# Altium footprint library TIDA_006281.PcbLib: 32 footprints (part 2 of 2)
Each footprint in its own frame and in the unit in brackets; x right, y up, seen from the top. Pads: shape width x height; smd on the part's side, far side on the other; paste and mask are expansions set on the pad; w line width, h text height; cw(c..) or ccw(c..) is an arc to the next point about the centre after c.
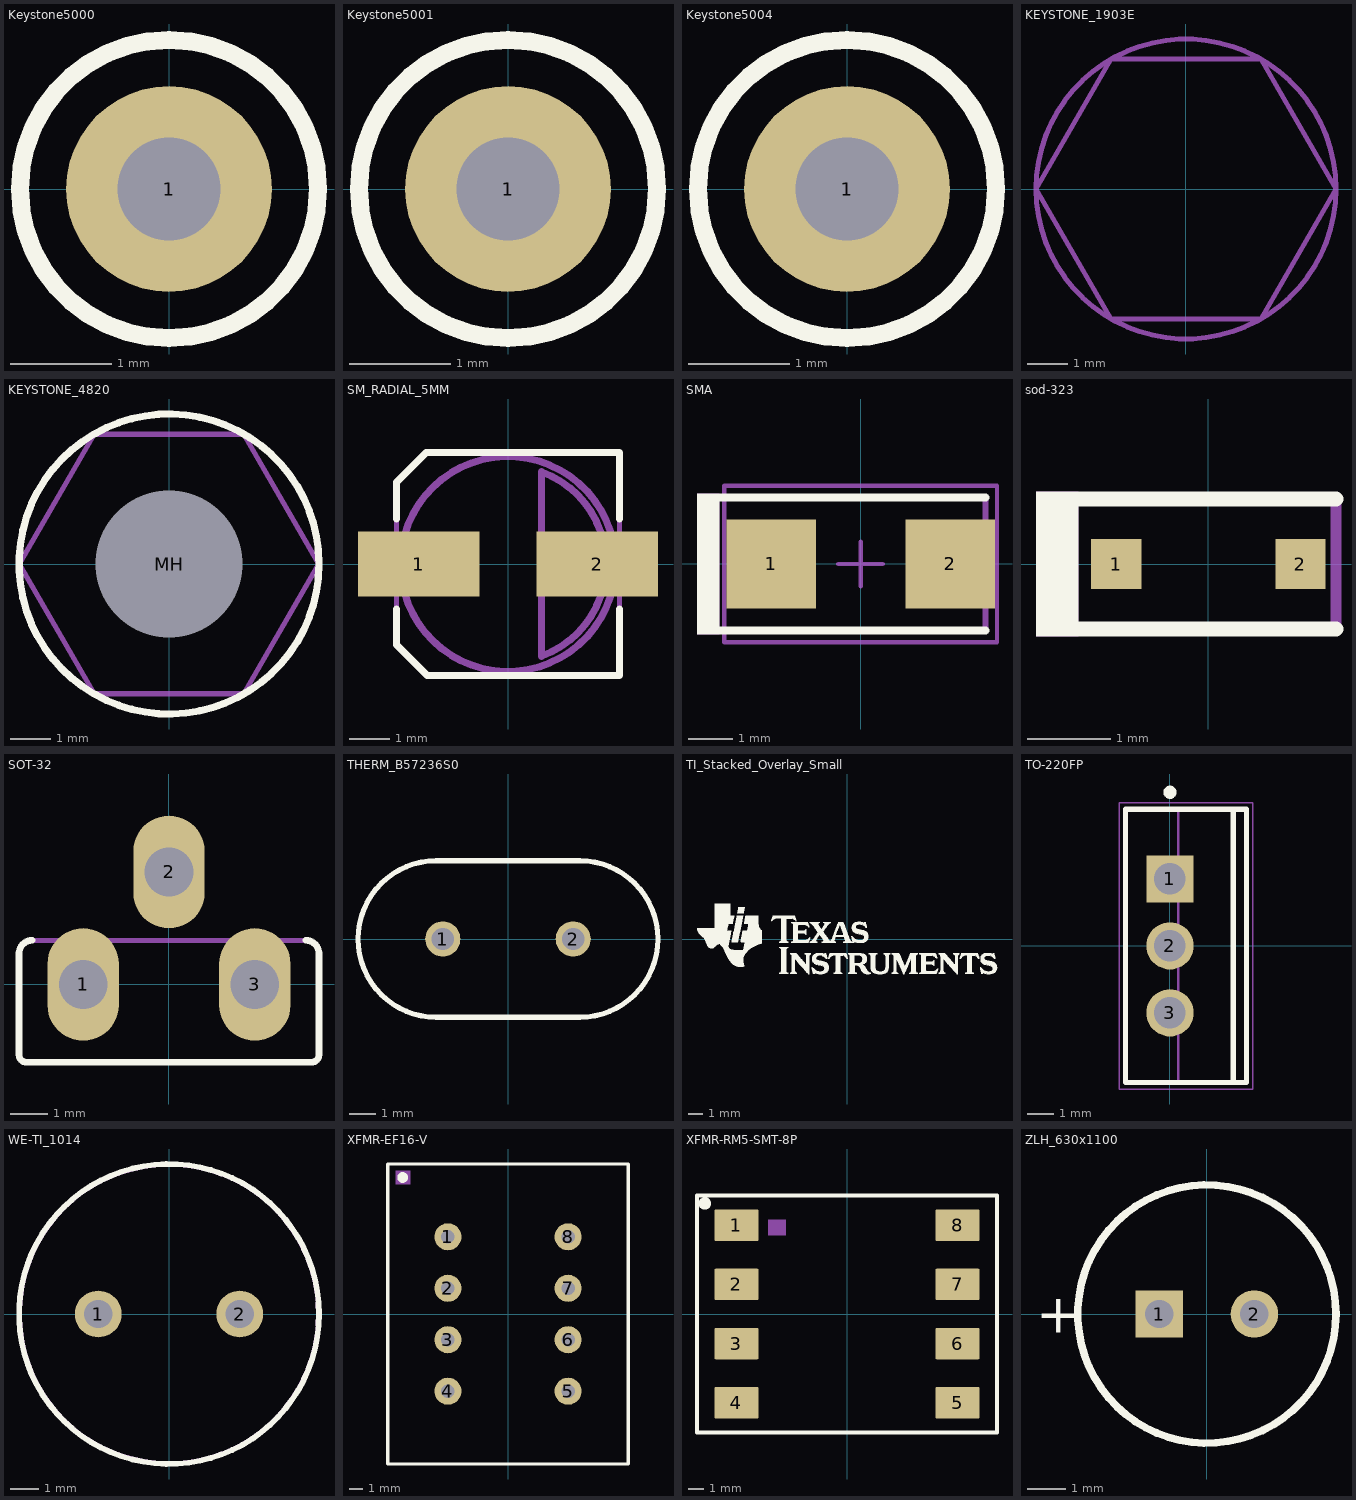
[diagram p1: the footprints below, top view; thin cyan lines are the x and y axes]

## Keystone5000 [mil] "For Keystone 500x miniature loop terminals"
height 181.1
pads (1):
  round 80 hole 40: 1(0,0)
Top Overlay:
  circle w7: c0,0 r58
Mechanical 5:
  circle w5: c0,0 r58.31
  text ".Designator" at -45,-10 h30
3D body: height 181.97, standoff -118.11, extent -49,-49 49.04,49.23

## Keystone5001 [mil] "For Keystone 500x miniature loop terminals"
height 181.1
pads (1):
  round 80 hole 40: 1(0,0)
Top Overlay:
  circle w7: c0,0 r58
Mechanical 5:
  circle w5: c0,0 r58.31
  text ".Designator" at -45,-10 h30
3D body: height 181.97, standoff -118.11, extent -49,-49 49.04,49.24

## Keystone5004 [mil] "For Keystone 500x miniature loop terminals"
height 181.1
pads (1):
  round 80 hole 40: 1(0,0)
Top Overlay:
  circle w7: c0,0 r58
Mechanical 5:
  circle w5: c0,0 r58.31
  text ".Designator" at -45,-10 h30
3D body: height 181.97, standoff -118.11, extent -49,-49 49.04,49.23

## KEYSTONE_1903E [mil] "HEX NYLON STANDOFF 6-32, F-F 1\""
height 1000
pads (1):
  round 1 on Mech3: 0(0,0)
Mechanical 5:
  circle w5: c0,0 r147.71
  lines w5: -147.75,-0.05 -73.87,127.91 73.87,127.91 147.75,-0.05 73.87,-128 -73.87,-128 -147.75,-0.05
  text ".Designator" at -75,-19 h40
3D body: height 1000, standoff 0, extent -147.74,-127.95 147.75,127.96

## KEYSTONE_4820 [mm] "HEX NYLON STANDOFF 6-32, M-F 1\""
height 25.4
pads (2):
  round 0.025 on Mech3: 0(0,0)
  round 1 hole 3.6 unplated: MH(0,0)
Top Overlay:
  circle w0.178: c0,0 r3.67
Mechanical 5:
  circle w0.127: c0,0 r3.67
  lines w0.127: -3.666,0 -1.833,3.175 1.833,3.175 3.666,0 1.833,-3.175 -1.833,-3.175 -3.666,0
  text ".Designator" at -1.829,-0.457 h1.02
3D body: height 25.42, standoff -6.33, extent -3.666,-3.175 3.666,3.175

## SM_RADIAL_5MM [mm] "Nichicon 5x5.8"
height 6.1
pads (2):
  rect 3x1.6 smd: 1(-2.2,0) 2(2.2,0)
Top Overlay:
  lines w0.178: -2.75,-1.108 -2.75,-1.992 -1.992,-2.75 2.75,-2.75 2.75,-1.108 ; -2.75,1.108 -2.75,2.019 -2.019,2.75 2.75,2.75 2.75,1.118
Mechanical 5:
  lines w0.127: -2.75,-1.992 -2.75,2.019 -2.019,2.75 2.75,2.75 2.75,-2.75 -1.992,-2.75 -2.75,-1.992
  text ".Designator" at -1.9,-0.5 h1.02
Mechanical 13:
  circle w0.178: c0,0 r2.65
  lines w0.178: 0.827,-2.273 ccw(c0,0) 0.827,2.273 0.827,-2.273
3D body: height 6.1, standoff 1, extent -2.658,-2.658 2.658,2.658
3D body: height 6.1, standoff 6, extent 0.827,-2.277 2.432,2.277
3D body: height 1, standoff 0, extent -2.751,-2.751 2.751,2.751

## SMA [mm] "Molded Diode, 2-Leads, Body 4.3x2.6mm, IPC Medium Density, based on OnSemi component dimensions and land pattern"
height 2.27
pads (2):
  rect 2x2 smd: 1(-2,0) 2(2,0)
Top Overlay:
  rectangle: -3.658,-1.575 -3.15,1.575
  lines w0.178: -3.327,-1.486 2.794,-1.486 ; -3.327,1.486 2.794,1.486
Mechanical 5:
  rectangle: -3.658,-1.575 -3.15,1.575
  lines w0.127: -3.327,-1.486 2.794,-1.486 2.794,1.486 -3.327,1.486
  text ".Designator" at -2.769,-0.33 h1.02
Mechanical 15:
  lines w0.1: -0.5,0 0.5,0 ; 0,-0.5 0,0.5 ; -3.05,-1.75 -3.05,1.75 3.05,1.75 3.05,-1.75 -3.05,-1.75
3D body: height 2.42, standoff 0.02, extent -2.6,-1.3 2.6,1.3

## sod-323 [mm] "NXP recommended land pattern"
height 1.15
pads (2):
  rect 0.6x0.6 smd paste-0.05: 1(-1.1,0) 2(1.1,0)
Top Overlay:
  rectangle: -2.057,-0.864 -1.549,0.864
  lines w0.178: -1.803,-0.775 0.1,-0.775 1.525,-0.775 ; -1.803,0.775 0.1,0.775 1.525,0.775
Mechanical 5:
  rectangle: -2.057,-0.864 -1.549,0.864
  lines w0.127: -1.803,-0.775 0.1,-0.775 1.525,-0.775 1.525,0.775 0.1,0.775 -1.803,0.775
  text ".Designator" at -1.4,-0.275 h0.76
3D body: height 1.1, standoff 0, extent -1.3,-0.675 1.3,0.675

## SOT-32 [mm]
height 13
pads (3):
  oval 1.9x3 hole 1.3: 1(-2.29,0) 2(0,3) 3(2.29,0)
Top Overlay:
  lines w0.178: -3.65,1.175 ccw(c-3.65,0.825) -3.996,0.878 ccw(c-3.65,0.825) -4,0.825 -4,-1.845 -4,-1.875 ccw(c-3.8,-1.875) -3.8,-2.075 3.8,-2.075 ccw(c3.8,-1.875) 4,-1.875 4,-1.845 4,0.825 ccw(c3.65,0.825) 3.996,0.878 ccw(c3.65,0.825) 3.65,1.175
Mechanical 5:
  lines w0.127: -4,-1.875 ccw(c-3.8,-1.875) -3.8,-2.075 3.8,-2.075 ccw(c3.8,-1.875) 4,-1.875 4,-1.845 4,0.825 ccw(c3.65,0.825) 3.996,0.878 ccw(c3.65,0.825) 3.65,1.175 -3.65,1.175 ccw(c-3.65,0.825) -3.996,0.878 ccw(c-3.65,0.825) -4,0.825 -4,-1.845 -4,-1.875
  text ".Designator" at -1.875,-0.5 h1.02
3D body: height 13.13, standoff -4.98, extent -4,-2.073 4,1.177

## THERM_B57236S0 [mm] "EPCOS"
height 16
pads (2):
  round 1.35 hole 0.85: 1(-2.5,0) 2(2.5,0)
Top Overlay:
  lines w0.2: -2.75,-3 cw(c-2.75,0) -2.75,3 2.75,3 cw(c2.75,0) 2.75,-3 -2.75,-3
Mechanical 5:
  lines w0.1: -2.75,-3 cw(c-2.75,0) -2.75,3 2.75,3 cw(c2.75,0) 2.75,-3 -2.75,-3
  text ".Designator" at -4.024,-0.508 h1.02
3D body: height 15.99, standoff 4.51, extent -5.755,-3 5.7,3
3D body: height 5.5, standoff -2.5, extent 2.202,-0.299 2.8,0.3
3D body: height 5.5, standoff -2.5, extent -2.797,-0.299 -2.2,0.3

## TI_Stacked_Overlay_Small [mm]
Top Overlay:
  drawing of 18 lines, arcs and shapes, not listed

## TO-220FP [mm] "FM, Body 10.4x4.6mm, Pitch 2.55mm"
height 20
pads (3):
  rect 1.8x1.8 hole 1.2: 1(0,2.55)
  round 1.8 hole 1.2: 2(0,0) 3(0,-2.55)
Top Overlay:
  circle w0.25: c0,5.85 r0.125
  lines w0.2: 2.41,-5.2 2.41,5.2 ; -1.69,-5.2 -1.69,5.2 2.91,5.2 2.91,-5.2 -1.69,-5.2
Mechanical 5:
  lines w0.1: 0.31,-5.2 0.31,5.2 ; -1.69,-5.2 2.91,-5.2 2.91,5.2 -1.69,5.2 -1.69,-5.2
  text ".Designator" at 1.1,1.6 h1.02
Mechanical 15:
  lines w0.05: -1.94,-5.45 3.16,-5.45 3.16,5.45 -1.94,5.45 -1.94,-5.45
  lines w0.1: -0.5,0 0.5,0 ; 0,-0.5 0,0.5
3D body: height 20, standoff 18.15, extent 0.31,-5.1 2.91,5.1
3D body: height 16.91, standoff 16.6, extent 0.31,-5.1 2.91,-1.55
3D body: height 16.91, standoff 16.6, extent 0.31,1.55 2.91,5.1
3D body: height 16.6, standoff 16.3, extent 0.31,-5.1 2.91,-1.55
3D body: height 16.6, standoff 16.3, extent 0.31,1.55 2.91,5.1
3D body: height 17.2, standoff 16.9, extent 0.31,-5.1 2.91,-1.52
3D body: height 17.2, standoff 16.9, extent 0.31,1.52 2.91,5.1
3D body: height 16.3, standoff 16.01, extent 0.31,-5.1 2.91,-1.52
3D body: height 16.3, standoff 16.01, extent 0.31,1.52 2.91,5.1
3D body: height 17.47, standoff 17.19, extent 0.31,-5.1 2.91,-1.432
3D body: height 17.47, standoff 17.19, extent 0.31,1.432 2.91,5.1
3D body: height 16.01, standoff 15.74, extent 0.31,-5.1 2.91,-1.432
3D body: height 16.01, standoff 15.74, extent 0.31,1.432 2.91,5.1
3D body: height 17.7, standoff 17.46, extent 0.31,-5.1 2.91,-1.289
3D body: height 17.7, standoff 17.46, extent 0.31,1.289 2.91,5.1
3D body: height 15.74, standoff 15.5, extent 0.31,-5.1 2.91,-1.289
3D body: height 15.74, standoff 15.5, extent 0.31,1.289 2.91,5.1
3D body: height 17.89, standoff 17.7, extent 0.31,-5.1 2.91,-1.096
3D body: height 17.89, standoff 17.7, extent 0.31,1.096 2.91,5.1
3D body: height 15.51, standoff 15.31, extent 0.31,-5.1 2.91,-1.096
3D body: height 15.51, standoff 15.31, extent 0.31,1.096 2.91,5.1
3D body: height 18.04, standoff 17.89, extent 0.31,-5.1 2.91,-0.861
3D body: height 18.04, standoff 17.89, extent 0.31,0.861 2.91,5.1
3D body: height 15.32, standoff 15.17, extent 0.31,-5.1 2.91,-0.861
3D body: height 15.32, standoff 15.17, extent 0.31,0.861 2.91,5.1
3D body: height 18.13, standoff 18.03, extent 0.31,-5.1 2.91,-0.593
3D body: height 18.13, standoff 18.03, extent 0.31,0.593 2.91,5.1
3D body: height 15.17, standoff 15.08, extent 0.31,-5.1 2.91,-0.593
3D body: height 15.17, standoff 15.08, extent 0.31,0.593 2.91,5.1
3D body: height 18.15, standoff 18.12, extent 0.31,-5.1 2.91,-0.302
3D body: height 18.15, standoff 18.12, extent 0.31,0.302 2.91,5.1
3D body: height 15.08, standoff 15.05, extent 0.31,-5.1 2.91,-0.302
3D body: height 15.08, standoff 15.05, extent 0.31,0.302 2.91,5.1
3D body: height 15.05, standoff 13, extent 0.31,-5.1 2.91,5.1
3D body: height 13, standoff 2.5, extent -1.69,-5.2 2.91,5.2
3D body: height 0, standoff -1.6, extent -0.29,-2.99 0.29,-2.11
3D body: height 2.5, standoff 0, extent -0.29,-3.265 0.29,-1.835
3D body: height 0, standoff -1.6, extent -0.29,-0.44 0.29,0.44
3D body: height 2.5, standoff 0, extent -0.29,-0.715 0.29,0.715
3D body: height 0, standoff -1.6, extent -0.29,2.11 0.29,2.99
3D body: height 2.5, standoff 0, extent -0.29,1.835 0.29,3.265

## WE-TI_1014 [mm] "WURTH"
height 14.5
pads (2):
  round 1.65 hole 1: 1(-2.5,0) 2(2.5,0)
Top Overlay:
  circle w0.2: c0,0 r5.3
Mechanical 5:
  circle w0.1: c0,0 r5.25
  text ".Designator" at -1.8,-0.5 h1.02
3D body: height 14.5, standoff 13.5, extent -5.261,-5.261 5.261,5.261
3D body: height 13.5, standoff 4, extent -4.91,-4.91 4.91,4.91
3D body: height 4, standoff 0, extent -5.261,-5.261 5.261,5.261
3D body: height 1, standoff -2, extent -2.847,-0.349 -2.15,0.35
3D body: height 1, standoff -2, extent 2.153,-0.349 2.85,0.35

## XFMR-EF16-V [mm]
pads (8):
  round 2 hole 1: 1(-4.445,5.715) 2(-4.445,1.905) 3(-4.445,-1.905) 4(-4.445,-5.715) 5(4.445,-5.715) 6(4.445,-1.905) 7(4.445,1.905) 8(4.445,5.715)
Top Overlay:
  circle w0.381: c-7.8,10.1 r0.203
  lines w0.25: -8.89,-11.1 -8.89,11.1 8.89,11.1 8.89,-11.1 -8.89,-11.1
Mechanical 5:
  rectangle: -8.343,9.6 -7.2,10.616
  lines w0.127: -8.89,-11.1 8.89,-11.1 8.89,11.1 -8.89,11.1 -8.89,-11.1
  text ".Designator" at -3.175,-0.127 h1.02

## XFMR-RM5-SMT-8P [mm]
height 5.8
pads (8):
  rrect10% 2.8x2 smd: 1(-7,5.625) 2(-7,1.875) 3(-7,-1.875) 4(-7,-5.625) 5(7,-5.625) 6(7,-1.875) 7(7,1.875) 8(7,5.625)
Top Overlay:
  circle w0.381: c-9,7 r0.203
  lines w0.25: -9.5,-7.5 9.5,-7.5 9.5,7.5 -9.5,7.5 -9.5,-7.5
Mechanical 5:
  rectangle: -5,4.984 -3.857,6
  lines w0.127: -9.5,-7.5 -9.5,7.5 9.5,7.5 9.5,-7.5 -9.5,-7.5
  text ".Designator" at -3.175,-0.127 h1.02

## ZLH_630x1100 [mm] "Radial Leaded, 2-Leads, Dia 6.3mm, Height 11mm, Pin Spacing 2.5mm"
height 12.5
pads (2):
  rect 1.25x1.25 hole 0.75: 1(-1.25,0)
  round 1.25 hole 0.75: 2(1.25,0)
Top Overlay:
  circle w0.2: c0,0 r3.4
  text "+" at -4.5,-0.5 h1.02
Mechanical 5:
  circle w0.1: c0,0 r3.4
  text ".Designator" at -2,-0.5 h1.02
  text "+" at -4.5,-0.5 h1.02
3D body: height 12.51, standoff -4, extent -3.373,-3.394 3.397,3.395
